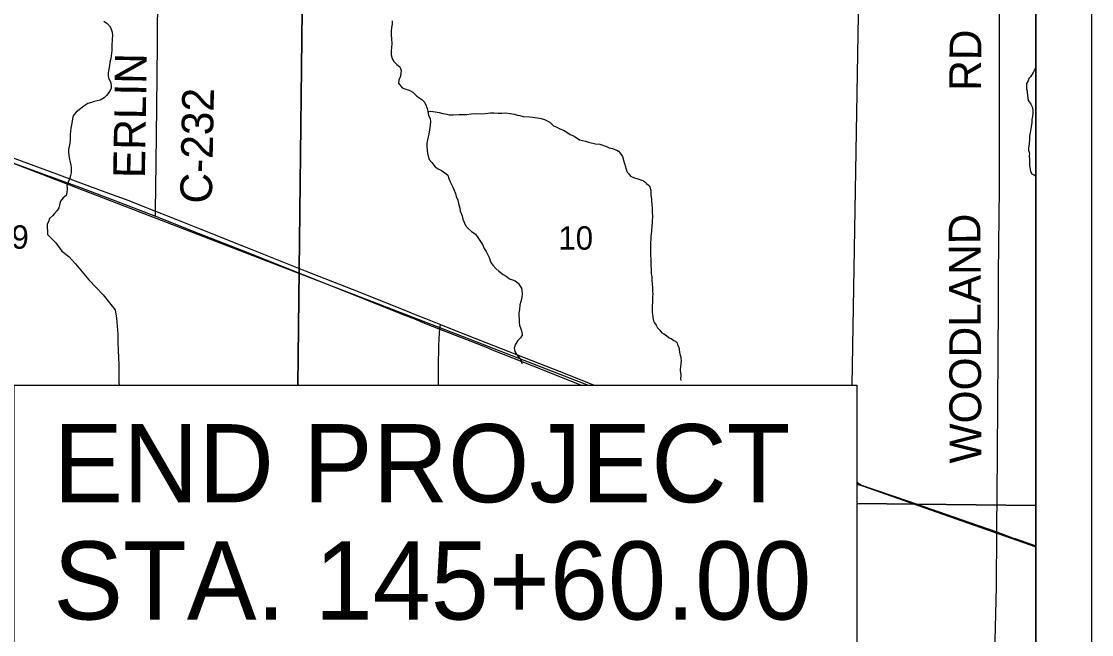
# Model space of a CAD drawing. Extents: x 0 to 34, y 0 to 22.
# Drawn here: x 28.499 to 30.417, y 17.692 to 18.79 of the extents above; entities that cross this region are included whole.
import ezdxf

# ---------------------------------------------------------------- set-up
doc = ezdxf.new("R2010")
doc.units = 0
for name, color, linetype in [('GM_X_County_Road', 7, 'Continuous'), ('GM_X_County_Road_Text', 7, 'Continuous'), ('GM_X_Minor_River', 7, 'Continuous'), ('GM_X_Rail_Line', 7, 'Continuous'), ('GM_X_Section', 7, 'Continuous'), ('GM_X_Section_Text', 7, 'Continuous'), ('GM_X_Township_Road', 7, 'Continuous'), ('GM_X_Township_Road_Text', 7, 'Continuous'), ('GM_X_US_Route', 7, 'Continuous'), ('SH_Data', 7, 'Continuous'), ('SH_Text', 7, 'Continuous')]:
    doc.layers.add(name, color=color, linetype=linetype)

msp = doc.modelspace()

# ---------------------------------------------------------------- linework, layer by layer
at = {"layer": 'GM_X_County_Road'}
for points in [[(28.739, 18.4414), (28.7392, 18.4501), (28.7405, 18.537), (28.7417, 18.6373), (28.7429, 18.7487), (28.7437, 18.8464), (28.7439, 18.9139), (28.7525, 19.4249)], [(30.2399, 17.4918), (30.2407, 17.5371), (30.2429, 17.6314), (30.2461, 17.7776), (30.2468, 17.8756)]]:
    msp.add_lwpolyline(points, dxfattribs=at)
at = {"layer": 'GM_X_Minor_River'}
for points in [[(28.6466, 18.7905), (28.6526, 18.7866), (28.6571, 18.7824), (28.6594, 18.7782), (28.6619, 18.7706), (28.6622, 18.7649), (28.6618, 18.7588), (28.6613, 18.7459), (28.6612, 18.7379), (28.6595, 18.7235), (28.6575, 18.7171), (28.6567, 18.711), (28.6546, 18.6978), (28.6546, 18.6936), (28.6553, 18.6887), (28.6575, 18.6845), (28.6594, 18.6803), (28.6601, 18.6749), (28.6596, 18.6704), (28.6573, 18.6651), (28.6515, 18.6576), (28.6473, 18.6534), (28.6401, 18.6493), (28.6294, 18.6468), (28.6248, 18.645), (28.618, 18.6431), (28.6107, 18.6383), (28.6054, 18.6342), (28.5969, 18.6274), (28.5931, 18.6225), (28.5911, 18.6184), (28.5887, 18.6047), (28.5875, 18.5987), (28.5867, 18.593), (28.5863, 18.5884), (28.5861, 18.5782), (28.5857, 18.5721), (28.5845, 18.5661), (28.5833, 18.5608), (28.5832, 18.5562), (28.5839, 18.5497), (28.5853, 18.5425)], [(29.1636, 18.791), (29.1632, 18.7853), (29.1624, 18.7789), (29.1615, 18.7728), (29.1618, 18.7656), (29.1621, 18.7591), (29.1628, 18.7504), (29.1623, 18.7436), (29.1615, 18.7371), (29.1618, 18.7303), (29.1633, 18.7238), (29.1662, 18.7185), (29.1719, 18.7131), (29.1771, 18.7085), (29.1793, 18.7028), (29.1781, 18.6918), (29.1753, 18.685), (29.1749, 18.6797), (29.1812, 18.6709), (29.1861, 18.6693), (29.1941, 18.6669), (29.2005, 18.6631), (29.2076, 18.6562), (29.2163, 18.65), (29.2211, 18.6454), (29.2245, 18.6389), (29.2263, 18.6339), (29.227, 18.6286), (29.2285, 18.6222), (29.2314, 18.6157), (29.2318, 18.6107), (29.2313, 18.6043), (29.2304, 18.5959), (29.2292, 18.5884), (29.2276, 18.5834), (29.2264, 18.5781), (29.2256, 18.5713), (29.2255, 18.566), (29.2262, 18.5592)], [(30.3167, 18.7075), (30.3164, 18.7071), (30.3122, 18.6988), (30.3089, 18.6938), (30.307, 18.6908), (30.3043, 18.6877), (30.3028, 18.6835), (30.3002, 18.6789), (30.3002, 18.6691), (30.301, 18.6649), (30.3014, 18.6615), (30.3018, 18.6584), (30.3022, 18.652), (30.3038, 18.6478), (30.308, 18.6418), (30.3099, 18.6372), (30.3111, 18.6319), (30.3111, 18.6262), (30.3107, 18.6197), (30.31, 18.6171), (30.3096, 18.614), (30.3093, 18.6091), (30.3082, 18.6015), (30.3067, 18.5905), (30.3056, 18.5848), (30.3052, 18.5795), (30.3053, 18.5768), (30.3049, 18.573), (30.3049, 18.57), (30.3038, 18.5635), (30.3038, 18.5593), (30.305, 18.5559), (30.3054, 18.5525), (30.305, 18.5498), (30.3051, 18.5419), (30.3054, 18.5388), (30.3055, 18.532), (30.3063, 18.5255), (30.3074, 18.5214), (30.3094, 18.5172), (30.3143, 18.5145), (30.3167, 18.5131)], [(29.2273, 18.6274), (29.2296, 18.629), (29.2323, 18.6294), (29.2364, 18.6287), (29.2402, 18.6283), (29.2474, 18.6272), (29.2539, 18.6253), (29.2611, 18.6238), (29.2653, 18.6227), (29.2729, 18.6228), (29.2835, 18.6232), (29.2907, 18.6232), (29.2972, 18.6236), (29.3048, 18.6248), (29.3146, 18.6252), (29.323, 18.6245), (29.3302, 18.6253), (29.3393, 18.6261), (29.3458, 18.6265), (29.3534, 18.6258), (29.3598, 18.6258), (29.3659, 18.6262), (29.3746, 18.6251), (29.3826, 18.6237), (29.3875, 18.6222), (29.3921, 18.6214), (29.3982, 18.6199), (29.4103, 18.6189), (29.4236, 18.6174), (29.4301, 18.6159), (29.4362, 18.6144), (29.4461, 18.6095), (29.4522, 18.6031), (29.4586, 18.6005), (29.4636, 18.5975), (29.4701, 18.5952), (29.4765, 18.5918), (29.4822, 18.5877), (29.4895, 18.5843), (29.499, 18.5779), (29.5096, 18.5756), (29.5153, 18.5738), (29.5275, 18.5708), (29.5355, 18.5701), (29.5393, 18.569), (29.5438, 18.5671), (29.5465, 18.5667), (29.5522, 18.5637), (29.5579, 18.5622), (29.5621, 18.5607), (29.5659, 18.5592), (29.5689, 18.5577), (29.572, 18.5539), (29.5762, 18.5479), (29.5793, 18.5376), (29.5801, 18.5338), (29.5808, 18.5312), (29.5824, 18.5255), (29.5843, 18.5198), (29.5874, 18.5171), (29.5904, 18.513), (29.5961, 18.5107), (29.6056, 18.5074), (29.6106, 18.5055), (29.6136, 18.5047), (29.6163, 18.5029), (29.6193, 18.4998), (29.6228, 18.4968), (29.6251, 18.4942), (29.627, 18.4858), (29.627, 18.479), (29.6278, 18.4714), (29.6278, 18.468), (29.6286, 18.4626), (29.629, 18.4551), (29.6295, 18.4494), (29.6299, 18.4402), (29.6295, 18.4338), (29.6292, 18.4296), (29.6284, 18.4235), (29.6281, 18.4152), (29.6274, 18.4087), (29.627, 18.4053), (29.6266, 18.4022), (29.6263, 18.3912), (29.6264, 18.37), (29.6268, 18.3654), (29.6269, 18.3521), (29.6273, 18.3468), (29.6277, 18.3384), (29.6285, 18.3324), (29.6289, 18.3278), (29.6289, 18.3252), (29.6293, 18.3206), (29.6298, 18.3122), (29.6298, 18.3073), (29.6302, 18.3016), (29.6298, 18.2982), (29.6299, 18.2887), (29.6299, 18.2853), (29.6295, 18.2826)], [(29.2262, 18.5592), (29.2265, 18.5538), (29.228, 18.5489), (29.2295, 18.5428), (29.2343, 18.5371), (29.2407, 18.5298), (29.2456, 18.5263), (29.2516, 18.5228), (29.258, 18.519), (29.2633, 18.5144), (29.2651, 18.5086), (29.2681, 18.5014), (29.2714, 18.4942), (29.2736, 18.4892), (29.2769, 18.4816), (29.278, 18.4766), (29.281, 18.4698), (29.2824, 18.4637), (29.2846, 18.4557), (29.2853, 18.45), (29.2886, 18.4416), (29.2901, 18.4359), (29.2949, 18.4248), (29.2997, 18.4191), (29.305, 18.4145), (29.3129, 18.4091), (29.3181, 18.401), (29.3218, 18.3957), (29.3252, 18.3907), (29.3281, 18.3831), (29.3319, 18.3777), (29.3345, 18.372), (29.3374, 18.3671), (29.3404, 18.3583), (29.3437, 18.3533), (29.3494, 18.3472), (29.3546, 18.343), (29.3621, 18.3368), (29.3674, 18.3337), (29.3734, 18.3291), (29.3787, 18.3271), (29.384, 18.3256), (29.3889, 18.321), (29.3949, 18.3122), (29.3963, 18.3034), (29.3958, 18.2951), (29.3938, 18.2886), (29.3922, 18.2822), (29.3914, 18.2742), (29.3905, 18.2678), (29.3905, 18.2625), (29.3908, 18.2572), (29.3911, 18.2507), (29.3918, 18.2458), (29.394, 18.2393), (29.3955, 18.2336), (29.3962, 18.2283), (29.3931, 18.2234), (29.3885, 18.2185), (29.3842, 18.2117), (29.3819, 18.2045), (29.3833, 18.1988), (29.3866, 18.1927), (29.3915, 18.1869), (29.3945, 18.182), (29.396, 18.177)], [(28.5853, 18.5425), (28.5864, 18.5379), (28.5875, 18.5326), (28.5882, 18.5281), (28.5881, 18.5189), (28.5869, 18.514), (28.5849, 18.5076), (28.583, 18.5023), (28.5803, 18.4963), (28.5809, 18.4898), (28.5801, 18.4834), (28.5793, 18.4784), (28.5736, 18.4743), (28.5693, 18.4679), (28.567, 18.4615), (28.5658, 18.4562), (28.5631, 18.4513), (28.5584, 18.446), (28.5546, 18.4419), (28.5496, 18.437), (28.5473, 18.4309), (28.545, 18.4266)], [(28.545, 18.4266), (28.5455, 18.4086), (28.5609, 18.3932), (28.5713, 18.3787), (28.5837, 18.3691), (28.5957, 18.3557), (28.6081, 18.3415), (28.6197, 18.3273), (28.6328, 18.3135), (28.6455, 18.3001), (28.6567, 18.2859), (28.6672, 18.2733), (28.6693, 18.2588), (28.672, 18.23), (28.6719, 18.2163), (28.6725, 18.2007), (28.6731, 18.1878), (28.6733, 18.1749), (28.6735, 18.1609), (28.6737, 18.1438), (28.6741, 18.1387)], [(29.6295, 18.2826), (29.6292, 18.2739), (29.6292, 18.2682), (29.6296, 18.2655), (29.6304, 18.2595), (29.6316, 18.2538), (29.6335, 18.2504), (29.6365, 18.2458), (29.6388, 18.2409), (29.643, 18.2371), (29.6461, 18.2326), (29.6499, 18.2307), (29.6548, 18.2273), (29.6598, 18.2231), (29.6632, 18.222), (29.6678, 18.2186), (29.6708, 18.2171), (29.6739, 18.2141), (29.6747, 18.211), (29.677, 18.2065), (29.6774, 18.2023), (29.6785, 18.197), (29.6793, 18.1921), (29.6805, 18.189), (29.6809, 18.1856), (29.6813, 18.183), (29.6809, 18.1773), (29.6798, 18.1708), (29.6794, 18.1674), (29.6795, 18.1647), (29.6802, 18.1606), (29.6806, 18.1579), (29.6806, 18.1545), (29.6803, 18.1507), (29.6807, 18.1469)]]:
    msp.add_lwpolyline(points, dxfattribs=at)
at = {"layer": 'GM_X_Rail_Line'}
for points in [[(24.6857, 19.9193), (25.0148, 19.7985), (25.4772, 19.6296), (26.0332, 19.4244), (26.618, 19.2083), (27.1754, 19.0083), (27.8265, 18.7785), (28.397, 18.5695), (29.2915, 18.2251), (29.5147, 18.1387)], [(29.9962, 17.962), (30.1402, 17.9108), (30.3167, 17.8487)]]:
    msp.add_lwpolyline(points, dxfattribs=at)
at = {"layer": 'GM_X_Section'}
for points in [[(28.4862, 17.9139), (27.9928, 17.9132), (28.001, 18.9217), (29.0034, 18.9139), (28.9945, 18.1387)], [(28.9945, 18.1387), (29.0034, 18.9139), (30.0004, 18.9065), (29.9873, 18.1387)], [(29.9962, 17.9263), (30.3167, 17.9232), (30.3167, 18.9058), (30.0004, 18.9065), (29.9873, 18.1387)], [(29.976, 17.4387), (29.9677, 16.9066), (30.3167, 16.9046), (30.3167, 17.9232), (29.9962, 17.9263)]]:
    msp.add_lwpolyline(points, dxfattribs=at)
at = {"layer": 'GM_X_Township_Road'}
msp.add_line((29.246, 18.1387), (29.2461, 18.1389), dxfattribs=at)
for points in [[(30.2501, 18.3387), (30.2517, 18.4916), (30.2517, 18.7656), (30.2519, 18.9106)], [(30.2483, 18.0133), (30.2483, 18.0162), (30.2496, 18.2824), (30.2501, 18.3387)], [(29.2461, 18.1389), (29.2465, 18.171), (29.2471, 18.2102), (29.2479, 18.2315), (29.2486, 18.2388), (29.2501, 18.247)], [(30.2468, 17.8756), (30.2468, 17.8788), (30.2483, 18.0133)]]:
    msp.add_lwpolyline(points, dxfattribs=at)
at = {"layer": 'GM_X_US_Route'}
for p in [(29.9962, 17.9646), (29.9962, 17.9603)]:
    msp.add_line(p, (30.0045, 17.9595), dxfattribs=at)
for points in [[(27.9972, 18.7243), (28.0386, 18.7093), (28.0875, 18.6912), (28.1814, 18.6568), (28.2235, 18.6413), (28.2808, 18.6202), (28.33, 18.6021), (28.3853, 18.5817), (28.4645, 18.5527), (28.4986, 18.5401), (28.5214, 18.5318), (28.562, 18.5169), (28.6051, 18.5011), (28.6487, 18.485), (28.6914, 18.469), (28.7198, 18.4578), (28.7392, 18.4501), (28.7759, 18.4356), (28.8173, 18.4191), (28.909, 18.3828), (29.0076, 18.3435), (29.0917, 18.3102), (29.1829, 18.2741), (29.2048, 18.2652)], [(27.9971, 18.7155), (28.0868, 18.6828), (28.1999, 18.6412), (28.2925, 18.6071), (28.3847, 18.5733), (28.4626, 18.5445), (28.4979, 18.5316), (28.5192, 18.5239), (28.5618, 18.5082), (28.6048, 18.4923), (28.647, 18.4766), (28.6897, 18.4603), (28.7188, 18.4491), (28.739, 18.4414), (28.8158, 18.4109), (28.9075, 18.3747), (29.0061, 18.3354), (29.0902, 18.3021), (29.1814, 18.2659), (29.2033, 18.2571)], [(29.2033, 18.2571), (29.2215, 18.2497), (29.2486, 18.2388), (29.3335, 18.2057), (29.3428, 18.202)], [(29.2048, 18.2652), (29.223, 18.2579), (29.2501, 18.247)], [(29.2501, 18.247), (29.275, 18.2373), (29.3312, 18.215), (29.3723, 18.1988), (29.4271, 18.1773), (29.4625, 18.1635), (29.515, 18.1429), (29.5256, 18.1387)], [(29.3428, 18.202), (29.4323, 18.1663), (29.502, 18.1387)], [(30.0045, 17.9595), (30.0885, 17.9306), (30.183, 17.8979), (30.2468, 17.8756), (30.2751, 17.8653)], [(30.2751, 17.8653), (30.2799, 17.8636), (30.3167, 17.8507)]]:
    msp.add_lwpolyline(points, dxfattribs=at)
at = {"layer": 'SH_Data'}
for points in [[(23.4167, 21), (30.4167, 21), (30.4167, 14), (23.4167, 14)], [(23.5167, 20.9), (30.3167, 20.9), (30.3167, 14.1), (23.5167, 14.1)], [(28.4862, 18.1387), (29.9962, 18.1387), (29.9962, 17.4387), (28.4862, 17.4387)]]:
    msp.add_lwpolyline(points, close=True, dxfattribs=at)

# ---------------------------------------------------------------- texts
at = {"layer": 'GM_X_County_Road_Text'}
for s, rotation, p in [('ERLIN', 89.0651, (28.7202, 18.509)), ('C-232', 88.8978, (28.8402, 18.4634))]:
    msp.add_text(s, height=0.05682, rotation=rotation, dxfattribs=at).set_placement(p)
at = {"layer": 'GM_X_Section_Text'}
for s, height, p in [('9', 0.0419, (28.4811, 18.3829)), ('10', 0.04186, (29.4611, 18.3812))]:
    msp.add_text(s, height=height, rotation=0, dxfattribs=at).set_placement(p)
at = {"layer": 'GM_X_Township_Road_Text'}
for s, rotation, p in [('RD', 89.5045, (30.2183, 18.6655)), ('WOODLAND', 90.2333, (30.2192, 17.9984))]:
    msp.add_text(s, height=0.05682, rotation=rotation, dxfattribs=at).set_placement(p)
at = {"layer": 'SH_Text'}
for s, p in [('END PROJECT', (28.5562, 17.9287)), ('STA. 145+60.00', (28.5562, 17.7187))]:
    msp.add_text(s, height=0.14, dxfattribs=at).set_placement(p)

doc.saveas('drawing.dxf')
